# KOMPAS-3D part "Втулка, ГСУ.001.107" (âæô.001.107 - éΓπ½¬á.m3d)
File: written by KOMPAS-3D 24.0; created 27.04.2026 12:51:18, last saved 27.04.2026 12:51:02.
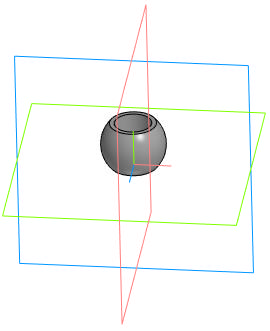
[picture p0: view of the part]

Document properties: Автор: User7; Полное имя файла: C:\Users\User7\Desktop\олимп\ГСУ.001.107 - Втулка.m3d

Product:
- Part/product: Втулка  | designation ГСУ.001.107
    Масса: 0.00612

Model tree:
1. Эскиз:1
2. Элемент вращения:1
     Угол 1 = 360

Expressions: 14.6/2
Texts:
  ГСУ.001.107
